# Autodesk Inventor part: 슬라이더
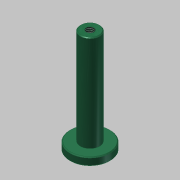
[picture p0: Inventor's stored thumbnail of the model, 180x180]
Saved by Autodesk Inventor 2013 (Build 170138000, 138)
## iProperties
Created: 2016-02
Part Number: 슬라이더
Material: 스테인리스강
Document SubType Name: Modeling
Designer: mduedu
Density: 8.08 g/cm^3
Author: mduedu
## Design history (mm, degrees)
sketch "스케치1"
  geometry: C1 r 12.5 at (0, 0); 1 further point
  constraints: 1 centre point, 1 coincident
  dimensions: "d0" = 25 diameter of C1
extrude "돌출1" new body sketch "스케치1" distance "d1" = 5; taper "d2" = 0 deg
sketch "스케치2"
  geometry: C1 r 6 at (0, 0); 1 further point
  constraints: 1 centre point, 1 coincident
  dimensions: "d3" = 12 diameter of C1
extrude "돌출2" join sketch "스케치2" distance "d4" = 60; taper "d5" = 0 deg
chamfer "모따기1" distance "d6" = 0.5; stored, may be unused: second distance "d7" = 2, angle "d8" = 45 deg
hole "구멍1" diameter "d11" = 4.917; stored, may be unused: countersink angle "d15" = 90 deg, drill point angle "d17" = 118 deg; dims "d9" = 10, "d10" = 10, "d12" = 10, "d13" = 4, "d14" = 2, "d16" = 12
chamfer "모따기2" distance "d18" = 0.5; stored, may be unused: second distance "d19" = 2, angle "d20" = 45 deg
sketch "스케치3"
  geometry: L1 (-12.5, 4.5)-(-12, 5) reference; L2 (-12, 5)-(-6, 5) reference; L3 (-6, 5)-(-6, 64.5) reference; L4 (-6, 64.5)-(-5.5, 65) reference; L5 (-5.5, 65)-(-2.458, 65) reference; L6 (-2.458, 65)-(-2.458, 53) reference; L7 (-2.458, 53)-(0, 51.523) reference; L8 (0, 51.523)-(2.458, 53) reference; L9 (2.458, 53)-(2.458, 65) reference; L10 (2.458, 65)-(5.5, 65) reference; L11 (5.5, 65)-(6, 64.5) reference; L12 (6, 64.5)-(6, 5) reference; L13 (6, 5)-(12, 5) reference; L14 (12, 5)-(12.5, 4.5) reference; L15 (12.5, 4.5)-(12.5, 0.5) reference; L16 (12.5, 0.5)-(12, 0) reference; L17 (12, 0)-(-12, 0) reference; L18 (-12, 0)-(-12.5, 0.5) reference; L19 (-12.5, 0.5)-(-12.5, 4.5) reference; 1 further point
  node "절단 모서리 투영1"
node "솔리드1"
